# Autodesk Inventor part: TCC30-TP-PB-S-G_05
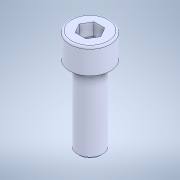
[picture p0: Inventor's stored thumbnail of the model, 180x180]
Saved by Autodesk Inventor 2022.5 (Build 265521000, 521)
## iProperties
Created: 2023-09
Part Number: TCC30-TP-PB-S-G_05
Material: 一般
Document SubType Name: Modeling
Designer: ImaoCorp
Density: 1 g/cm^3
Appearance: 既定
Author: ImaoCorp
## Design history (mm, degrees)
feature "TCC30-TP-PB-S-G_05"
node "ソリッド1"
